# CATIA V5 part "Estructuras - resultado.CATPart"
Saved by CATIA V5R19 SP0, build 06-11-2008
Part number: Estructuras - resultado
Bounding box of the stored display mesh (mm): x -165.206 to 53.773, y -15.481 to 36, z -5 to 20
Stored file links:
  G:\Prácticas\0068\68_v5r19\Estructuras - resultado.CATPart
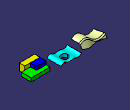
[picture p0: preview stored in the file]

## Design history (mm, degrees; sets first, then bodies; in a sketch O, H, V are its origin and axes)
Set1
  Sketch1 on zx-plane, origin (0, 0, 0), H (-1, 0, 0), V (0, 0, 1)
    spline S1 through (25.3759, 1.956) (35.7609, 8.1375) (48.124, 3.0687) (61.3525, 4.5522) (71.9847, 1.956) (83.606, 6.5303)
  Extrude1: Lim1 36, Lim2 5, Element1 Sketch1, Direction zx-plane
  Sketch2 on xy-plane, origin (0, 0, 0), H (1, 0, 0), V (0, 1, 0)
    circle A1 centre (-52.8527, 17.16) radius 9.9795
  Project1: Support Extrude1, Direction (0, 0, 1), ToProject Sketch2
  Split1: ToCut Extrude1, Cutting Project1
  Extrude2: Lim1 36, Lim2 5, Element1 Sketch2, Direction xy-plane
  Trim1: Trimmed (Split1; Extrude2)
  Set2
    Sketch3 on zx-plane, origin (0, 0, 0), H (-1, 0, 0), V (0, 0, 1)
      spline S1 through (25.3759, 1.956) (35.7609, 8.1375) (48.124, 3.0687) (61.3525, 4.5522) (71.9847, 1.956) (83.606, 6.5303)
    Extrude3: Lim1 36, Lim2 5, Element1 Sketch3, Direction zx-plane
    Sketch4 on xy-plane, origin (0, 0, 0), H (1, 0, 0), V (0, 1, 0)
      circle A1 centre (-52.8527, 17.16) radius 9.9795
    Project2: Support Extrude3, Direction (0, 0, 1), ToProject Sketch4
    Split2: ToCut Extrude3, Cutting Project2
    Extrude4: Lim1 36, Lim2 5, Element1 Sketch4, Direction xy-plane
    Trim2: Trimmed (Split2; Extrude4)
Set3
  Set4
    Sketch5 on zx-plane, origin (0, 0, 0), H (-1, 0, 0), V (0, 0, 1)
      spline S1 through (99.8383, 10.3678) (106.3011, 14.7785) (119.3682, 15.8789) (133.4063, 5.1188) (150.5796, 0.1019) (164.2796, 5.5048)
    Sweep1: type Segment, Angle 90, AngleEnd 100, Length1 35, Length2 10, DraftDirection (0, 0, 1), GuideCrv Sketch5
    CurvePar1: Support Sweep1, Offset1 12, Offset2 20, Offset edge of Sweep1
    Sweep2: type Segment, Angle 35, Length1 30, Length2 5, DraftDirection (0, 0, 1), GuideCrv CurvePar1
    Fillet1: type BiTangent, Element1 Sweep2, Element2 Sweep1, Radius 5
    Intersect1: ToIntersect1 xy-plane, ToIntersect2 Fillet1
    Extract1: ExtractElem edge of Intersect1
    Split3: ToCut Fillet1, Cutting Extract1
Body1 (main body)
  Sketch6 on xy-plane, origin (0, 0, 0), H (1, 0, 0), V (0, 1, 0)
    line L1 (0, 0) -> (53.7732, 0)
    line L2 (53.7732, 0) -> (53.7732, 28.7124)
    line L3 (53.7732, 28.7124) -> (0, 28.7124)
    line L4 (0, 28.7124) -> (0, 0)
    horizontal: L1 H, L3 H
    vertical: L2 V, L4 V
  Pad1: profile Sketch6, direction (0, 0, 1), length 10
Body2
  Sketch7 on end face of Pad1, origin (0, 0, 10), H (1, 0, 0), V (0, 1, 0)
    line L1 (0, 0) -> (27.5082, 0)
    line L2 (27.5082, 0) -> (27.5082, 17.7669)
    line L3 (27.5082, 17.7669) -> (0, 17.7669)
    line L4 (0, 17.7669) -> (0, 0)
    horizontal: L1 H, L3 H
    vertical: L2 V, L4 V
  Pad2: profile Sketch7, direction (0, 0, 1), length 10
  Fillet2: radius 5, on edge [face of Pad2 from Sketch7.L3 | face of Pad2 from Sketch7.L2]
Body3
  Body4
    Sketch8 on end face of Pad1, origin (0, 0, 10), H (1, 0, 0), V (0, 1, 0)
      line L1 (0, 0) -> (43.7446, 0)
      line L2 (43.7446, 0) -> (43.7446, -15.4814)
      line L3 (43.7446, -15.4814) -> (0, -15.4814)
      line L4 (0, -15.4814) -> (0, 0)
      horizontal: L1 H, L3 H
      vertical: L2 V, L4 V
    Pocket1: profile Sketch8, direction (0, 0, -1), length 10, mirrored extent
  Add1: tool Body4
